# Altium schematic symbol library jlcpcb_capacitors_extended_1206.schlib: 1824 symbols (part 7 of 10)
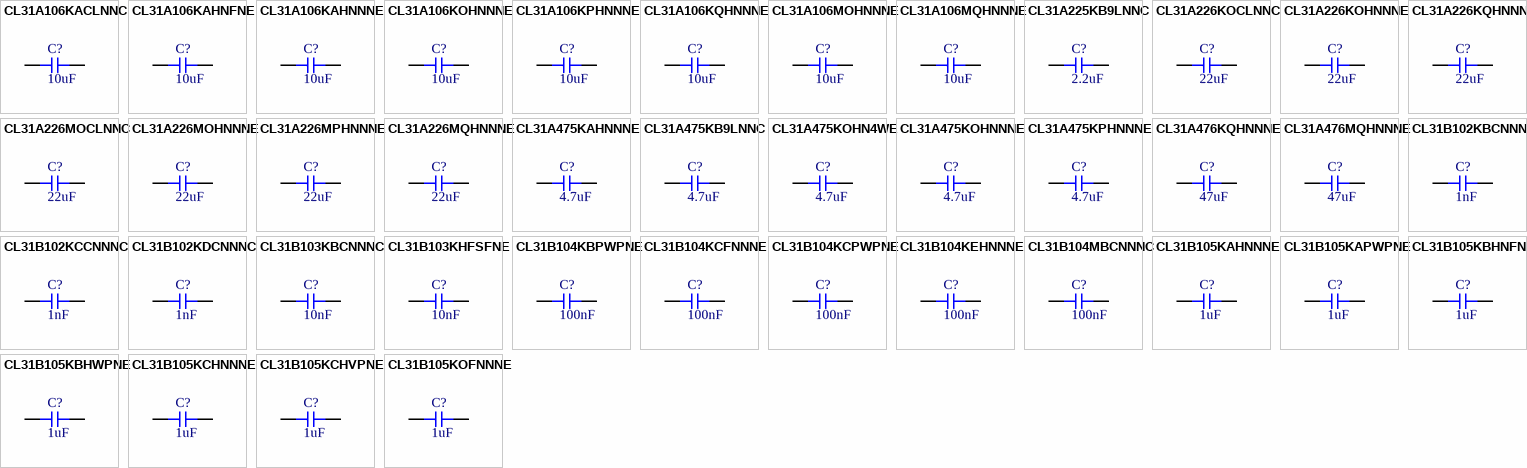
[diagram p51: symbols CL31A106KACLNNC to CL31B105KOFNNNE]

## CL31A475KAHNNNE
designator C?  Capacitance: 4.7uF  (hidden comment: *)
Capacitor, Ceramic (MLCC), 4.7uF, ±10%, 25V, X5R, ±10%, SMD 1206; Manufacturer: Samsung Electro-Mechanics; Manufacturer Part Number: CL31A475KAHNNNE
footprint CAP-1206 (1206 (3216M) Capacitor)
pins: 1, 2

## CL31A475KB9LNNC
designator C?  Capacitance: 4.7uF  (hidden comment: *)
Capacitor, Ceramic (MLCC), 4.7uF, ±10%, 50V, X5R, ±10%, SMD 1206; Manufacturer: Samsung Electro-Mechanics; Manufacturer Part Number: CL31A475KB9LNNC
footprint CAP-1206 (1206 (3216M) Capacitor)
pins: 1, 2

## CL31A475KOHN4WE
designator C?  Capacitance: 4.7uF  (hidden comment: *)
Capacitor, Ceramic (MLCC), 4.7uF, ±10%, 16V, X5R, ±10%, SMD 1206; Manufacturer: Samsung Electro-Mechanics; Manufacturer Part Number: CL31A475KOHN4WE
footprint CAP-1206 (1206 (3216M) Capacitor)
pins: 1, 2

## CL31A475KOHNNNE
designator C?  Capacitance: 4.7uF  (hidden comment: *)
Capacitor, Ceramic (MLCC), 4.7uF, ±10%, 16V, X5R, ±10%, SMD 1206; Manufacturer: Samsung Electro-Mechanics; Manufacturer Part Number: CL31A475KOHNNNE
footprint CAP-1206 (1206 (3216M) Capacitor)
pins: 1, 2

## CL31A475KPHNNNE
designator C?  Capacitance: 4.7uF  (hidden comment: *)
Capacitor, Ceramic (MLCC), 4.7uF, ±10%, 10V, X5R, ±10%, SMD 1206; Manufacturer: Samsung Electro-Mechanics; Manufacturer Part Number: CL31A475KPHNNNE
footprint CAP-1206 (1206 (3216M) Capacitor)
pins: 1, 2

## CL31A476KQHNNNE
designator C?  Capacitance: 47uF  (hidden comment: *)
Capacitor, Ceramic (MLCC), 47uF, ±10%, 6.3V, X5R, ±10%, SMD 1206; Manufacturer: Samsung Electro-Mechanics; Manufacturer Part Number: CL31A476KQHNNNE
footprint CAP-1206 (1206 (3216M) Capacitor)
pins: 1, 2

## CL31A476MQHNNNE
designator C?  Capacitance: 47uF  (hidden comment: *)
Capacitor, Ceramic (MLCC), 47uF, ±20%, 6.3V, X5R, ±20%, SMD 1206; Manufacturer: Samsung Electro-Mechanics; Manufacturer Part Number: CL31A476MQHNNNE
footprint CAP-1206 (1206 (3216M) Capacitor)
pins: 1, 2

## CL31B102KBCNNNC
designator C?  Capacitance: 1nF  (hidden comment: *)
Capacitor, Ceramic (MLCC), 1nF, ±10%, 50V, X7R, ±10%, SMD 1206; Manufacturer: Samsung Electro-Mechanics; Manufacturer Part Number: CL31B102KBCNNNC
footprint CAP-1206 (1206 (3216M) Capacitor)
pins: 1, 2

## CL31B102KCCNNNC
designator C?  Capacitance: 1nF  (hidden comment: *)
Capacitor, Ceramic (MLCC), 1nF, ±10%, 100V, X7R, ±10%, SMD 1206; Manufacturer: Samsung Electro-Mechanics; Manufacturer Part Number: CL31B102KCCNNNC
footprint CAP-1206 (1206 (3216M) Capacitor)
pins: 1, 2

## CL31B102KDCNNNC
designator C?  Capacitance: 1nF  (hidden comment: *)
Capacitor, Ceramic (MLCC), 1nF, ±10%, 200V, X7R, ±10%, SMD 1206; Manufacturer: Samsung Electro-Mechanics; Manufacturer Part Number: CL31B102KDCNNNC
footprint CAP-1206 (1206 (3216M) Capacitor)
pins: 1, 2

## CL31B103KBCNNNC
designator C?  Capacitance: 10nF  (hidden comment: *)
Capacitor, Ceramic (MLCC), 10nF, ±10%, 50V, X7R, ±10%, SMD 1206; Manufacturer: Samsung Electro-Mechanics; Manufacturer Part Number: CL31B103KBCNNNC
footprint CAP-1206 (1206 (3216M) Capacitor)
pins: 1, 2

## CL31B103KHFSFNE
designator C?  Capacitance: 10nF  (hidden comment: *)
Capacitor, Ceramic (MLCC), 10nF, ±10%, 630V, X7R, ±10%, SMD 1206; Manufacturer: Samsung Electro-Mechanics; Manufacturer Part Number: CL31B103KHFSFNE
footprint CAP-1206 (1206 (3216M) Capacitor)
pins: 1, 2

## CL31B104KBPWPNE
designator C?  Capacitance: 100nF  (hidden comment: *)
Capacitor, Ceramic (MLCC), 100nF, ±10%, 50V, X7R, ±10%, SMD 1206; Manufacturer: Samsung Electro-Mechanics; Manufacturer Part Number: CL31B104KBPWPNE
footprint CAP-1206 (1206 (3216M) Capacitor)
pins: 1, 2

## CL31B104KCFNNNE
designator C?  Capacitance: 100nF  (hidden comment: *)
Capacitor, Ceramic (MLCC), 100nF, ±10%, 100V, X7R, ±10%, SMD 1206; Manufacturer: Samsung Electro-Mechanics; Manufacturer Part Number: CL31B104KCFNNNE
footprint CAP-1206 (1206 (3216M) Capacitor)
pins: 1, 2

## CL31B104KCPWPNE
designator C?  Capacitance: 100nF  (hidden comment: *)
Capacitor, Ceramic (MLCC), 100nF, ±10%, 100V, X7R, ±10%, SMD 1206; Manufacturer: Samsung Electro-Mechanics; Manufacturer Part Number: CL31B104KCPWPNE
footprint CAP-1206 (1206 (3216M) Capacitor)
pins: 1, 2

## CL31B104KEHNNNE
designator C?  Capacitance: 100nF  (hidden comment: *)
Capacitor, Ceramic (MLCC), 100nF, ±10%, 250V, X7R, ±10%, SMD 1206; Manufacturer: Samsung Electro-Mechanics; Manufacturer Part Number: CL31B104KEHNNNE
footprint CAP-1206 (1206 (3216M) Capacitor)
pins: 1, 2

## CL31B104MBCNNNC
designator C?  Capacitance: 100nF  (hidden comment: *)
Capacitor, Ceramic (MLCC), 100nF, ±20%, 50V, X7R, ±20%, SMD 1206; Manufacturer: Samsung Electro-Mechanics; Manufacturer Part Number: CL31B104MBCNNNC
footprint CAP-1206 (1206 (3216M) Capacitor)
pins: 1, 2

## CL31B105KAHNNNE
designator C?  Capacitance: 1uF  (hidden comment: *)
Capacitor, Ceramic (MLCC), 1uF, ±10%, 25V, X7R, ±10%, SMD 1206; Manufacturer: Samsung Electro-Mechanics; Manufacturer Part Number: CL31B105KAHNNNE
footprint CAP-1206 (1206 (3216M) Capacitor)
pins: 1, 2

## CL31B105KAPWPNE
designator C?  Capacitance: 1uF  (hidden comment: *)
Capacitor, Ceramic (MLCC), 1uF, ±10%, 25V, X7R, ±10%, SMD 1206; Manufacturer: Samsung Electro-Mechanics; Manufacturer Part Number: CL31B105KAPWPNE
footprint CAP-1206 (1206 (3216M) Capacitor)
pins: 1, 2

## CL31B105KBHNFNE
designator C?  Capacitance: 1uF  (hidden comment: *)
Capacitor, Ceramic (MLCC), 1uF, ±10%, 50V, X7R, ±10%, SMD 1206; Manufacturer: Samsung Electro-Mechanics; Manufacturer Part Number: CL31B105KBHNFNE
footprint CAP-1206 (1206 (3216M) Capacitor)
pins: 1, 2

## CL31B105KBHWPNE
designator C?  Capacitance: 1uF  (hidden comment: *)
Capacitor, Ceramic (MLCC), 1uF, ±10%, 50V, X7R, ±10%, SMD 1206; Manufacturer: Samsung Electro-Mechanics; Manufacturer Part Number: CL31B105KBHWPNE
footprint CAP-1206 (1206 (3216M) Capacitor)
pins: 1, 2

## CL31B105KCHNNNE
designator C?  Capacitance: 1uF  (hidden comment: *)
Capacitor, Ceramic (MLCC), 1uF, ±10%, 100V, X7R, ±10%, SMD 1206; Manufacturer: Samsung Electro-Mechanics; Manufacturer Part Number: CL31B105KCHNNNE
footprint CAP-1206 (1206 (3216M) Capacitor)
pins: 1, 2

## CL31B105KCHVPNE
designator C?  Capacitance: 1uF  (hidden comment: *)
Capacitor, Ceramic (MLCC), 1uF, ±10%, 100V, X7R, ±10%, SMD 1206; Manufacturer: Samsung Electro-Mechanics; Manufacturer Part Number: CL31B105KCHVPNE
footprint CAP-1206 (1206 (3216M) Capacitor)
pins: 1, 2

## CL31B105KOFNNNE
designator C?  Capacitance: 1uF  (hidden comment: *)
Capacitor, Ceramic (MLCC), 1uF, ±10%, 16V, X7R, ±10%, SMD 1206; Manufacturer: Samsung Electro-Mechanics; Manufacturer Part Number: CL31B105KOFNNNE
footprint CAP-1206 (1206 (3216M) Capacitor)
pins: 1, 2

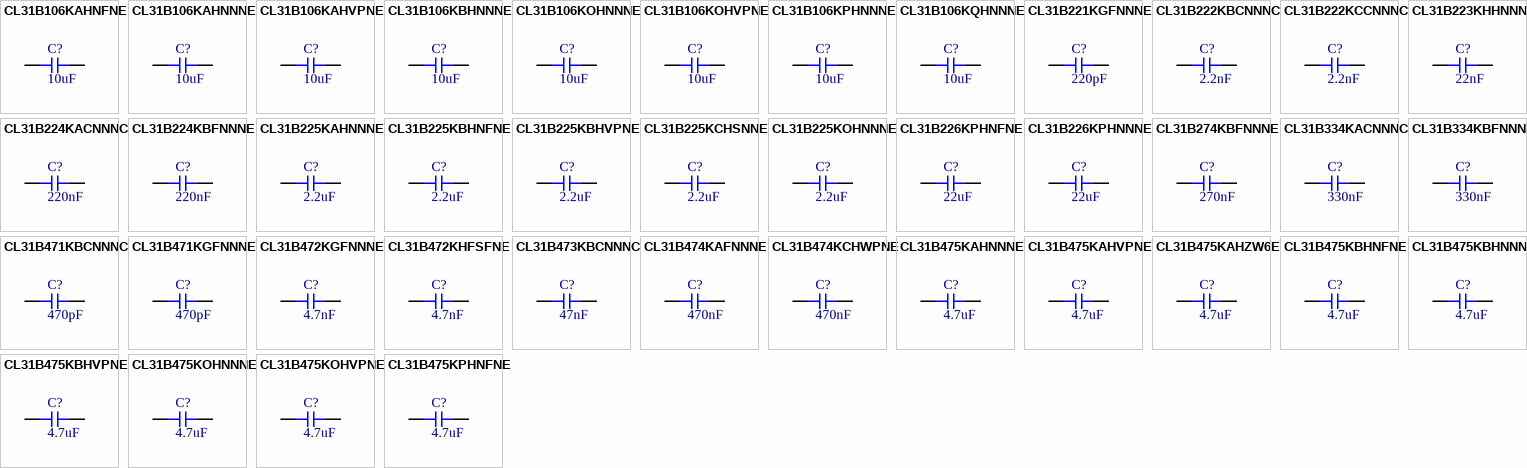
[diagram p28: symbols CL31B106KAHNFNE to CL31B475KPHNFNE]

## CL31B106KAHNFNE
designator C?  Capacitance: 10uF  (hidden comment: *)
Capacitor, Ceramic (MLCC), 10uF, ±10%, 25V, X7R, ±10%, SMD 1206; Manufacturer: Samsung Electro-Mechanics; Manufacturer Part Number: CL31B106KAHNFNE
footprint CAP-1206 (1206 (3216M) Capacitor)
pins: 1, 2

## CL31B106KAHNNNE
designator C?  Capacitance: 10uF  (hidden comment: *)
Capacitor, Ceramic (MLCC), 10uF, ±10%, 25V, X7R, ±10%, SMD 1206; Manufacturer: Samsung Electro-Mechanics; Manufacturer Part Number: CL31B106KAHNNNE
footprint CAP-1206 (1206 (3216M) Capacitor)
pins: 1, 2

## CL31B106KAHVPNE
designator C?  Capacitance: 10uF  (hidden comment: *)
Capacitor, Ceramic (MLCC), 10uF, ±10%, 25V, X7R, ±10%, SMD 1206; Manufacturer: Samsung Electro-Mechanics; Manufacturer Part Number: CL31B106KAHVPNE
footprint CAP-1206 (1206 (3216M) Capacitor)
pins: 1, 2

## CL31B106KBHNNNE
designator C?  Capacitance: 10uF  (hidden comment: *)
Capacitor, Ceramic (MLCC), 10uF, ±10%, 50V, X7R, ±10%, SMD 1206; Manufacturer: Samsung Electro-Mechanics; Manufacturer Part Number: CL31B106KBHNNNE
footprint CAP-1206 (1206 (3216M) Capacitor)
pins: 1, 2

## CL31B106KOHNNNE
designator C?  Capacitance: 10uF  (hidden comment: *)
Capacitor, Ceramic (MLCC), 10uF, ±10%, 16V, X7R, ±10%, SMD 1206; Manufacturer: Samsung Electro-Mechanics; Manufacturer Part Number: CL31B106KOHNNNE
footprint CAP-1206 (1206 (3216M) Capacitor)
pins: 1, 2

## CL31B106KOHVPNE
designator C?  Capacitance: 10uF  (hidden comment: *)
Capacitor, Ceramic (MLCC), 10uF, ±10%, 16V, X7R, ±10%, SMD 1206; Manufacturer: Samsung Electro-Mechanics; Manufacturer Part Number: CL31B106KOHVPNE
footprint CAP-1206 (1206 (3216M) Capacitor)
pins: 1, 2

## CL31B106KPHNNNE
designator C?  Capacitance: 10uF  (hidden comment: *)
Capacitor, Ceramic (MLCC), 10uF, ±10%, 10V, X7R, ±10%, SMD 1206; Manufacturer: Samsung Electro-Mechanics; Manufacturer Part Number: CL31B106KPHNNNE
footprint CAP-1206 (1206 (3216M) Capacitor)
pins: 1, 2

## CL31B106KQHNNNE
designator C?  Capacitance: 10uF  (hidden comment: *)
Capacitor, Ceramic (MLCC), 10uF, ±10%, 6.3V, X7R, ±10%, SMD 1206; Manufacturer: Samsung Electro-Mechanics; Manufacturer Part Number: CL31B106KQHNNNE
footprint CAP-1206 (1206 (3216M) Capacitor)
pins: 1, 2

## CL31B221KGFNNNE
designator C?  Capacitance: 220pF  (hidden comment: *)
Capacitor, Ceramic (MLCC), 220pF, ±10%, 500V, X7R, ±10%, SMD 1206; Manufacturer: Samsung Electro-Mechanics; Manufacturer Part Number: CL31B221KGFNNNE
footprint CAP-1206 (1206 (3216M) Capacitor)
pins: 1, 2

## CL31B222KBCNNNC
designator C?  Capacitance: 2.2nF  (hidden comment: *)
Capacitor, Ceramic (MLCC), 2.2nF, ±10%, 50V, X7R, ±10%, SMD 1206; Manufacturer: Samsung Electro-Mechanics; Manufacturer Part Number: CL31B222KBCNNNC
footprint CAP-1206 (1206 (3216M) Capacitor)
pins: 1, 2

## CL31B222KCCNNNC
designator C?  Capacitance: 2.2nF  (hidden comment: *)
Capacitor, Ceramic (MLCC), 2.2nF, ±10%, 100V, X7R, ±10%, SMD 1206; Manufacturer: Samsung Electro-Mechanics; Manufacturer Part Number: CL31B222KCCNNNC
footprint CAP-1206 (1206 (3216M) Capacitor)
pins: 1, 2

## CL31B223KHHNNNE
designator C?  Capacitance: 22nF  (hidden comment: *)
Capacitor, Ceramic (MLCC), 22nF, ±10%, 630V, X7R, ±10%, SMD 1206; Manufacturer: Samsung Electro-Mechanics; Manufacturer Part Number: CL31B223KHHNNNE
footprint CAP-1206 (1206 (3216M) Capacitor)
pins: 1, 2

## CL31B224KACNNNC
designator C?  Capacitance: 220nF  (hidden comment: *)
Capacitor, Ceramic (MLCC), 220nF, ±10%, 25V, X7R, ±10%, SMD 1206; Manufacturer: Samsung Electro-Mechanics; Manufacturer Part Number: CL31B224KACNNNC
footprint CAP-1206 (1206 (3216M) Capacitor)
pins: 1, 2

## CL31B224KBFNNNE
designator C?  Capacitance: 220nF  (hidden comment: *)
Capacitor, Ceramic (MLCC), 220nF, ±10%, 50V, X7R, ±10%, SMD 1206; Manufacturer: Samsung Electro-Mechanics; Manufacturer Part Number: CL31B224KBFNNNE
footprint CAP-1206 (1206 (3216M) Capacitor)
pins: 1, 2

## CL31B225KAHNNNE
designator C?  Capacitance: 2.2uF  (hidden comment: *)
Capacitor, Ceramic (MLCC), 2.2uF, ±10%, 25V, X7R, ±10%, SMD 1206; Manufacturer: Samsung Electro-Mechanics; Manufacturer Part Number: CL31B225KAHNNNE
footprint CAP-1206 (1206 (3216M) Capacitor)
pins: 1, 2

## CL31B225KBHNFNE
designator C?  Capacitance: 2.2uF  (hidden comment: *)
Capacitor, Ceramic (MLCC), 2.2uF, ±10%, 50V, X7R, ±10%, SMD 1206; Manufacturer: Samsung Electro-Mechanics; Manufacturer Part Number: CL31B225KBHNFNE
footprint CAP-1206 (1206 (3216M) Capacitor)
pins: 1, 2

## CL31B225KBHVPNE
designator C?  Capacitance: 2.2uF  (hidden comment: *)
Capacitor, Ceramic (MLCC), 2.2uF, ±10%, 50V, X7R, ±10%, SMD 1206; Manufacturer: Samsung Electro-Mechanics; Manufacturer Part Number: CL31B225KBHVPNE
footprint CAP-1206 (1206 (3216M) Capacitor)
pins: 1, 2

## CL31B225KCHSNNE
designator C?  Capacitance: 2.2uF  (hidden comment: *)
Capacitor, Ceramic (MLCC), 2.2uF, ±10%, 100V, X7R, ±10%, SMD 1206; Manufacturer: Samsung Electro-Mechanics; Manufacturer Part Number: CL31B225KCHSNNE
footprint CAP-1206 (1206 (3216M) Capacitor)
pins: 1, 2

## CL31B225KOHNNNE
designator C?  Capacitance: 2.2uF  (hidden comment: *)
Capacitor, Ceramic (MLCC), 2.2uF, ±10%, 16V, X7R, ±10%, SMD 1206; Manufacturer: Samsung Electro-Mechanics; Manufacturer Part Number: CL31B225KOHNNNE
footprint CAP-1206 (1206 (3216M) Capacitor)
pins: 1, 2

## CL31B226KPHNFNE
designator C?  Capacitance: 22uF  (hidden comment: *)
Capacitor, Ceramic (MLCC), 22uF, ±10%, 10V, X7R, ±10%, SMD 1206; Manufacturer: Samsung Electro-Mechanics; Manufacturer Part Number: CL31B226KPHNFNE
footprint CAP-1206 (1206 (3216M) Capacitor)
pins: 1, 2

## CL31B226KPHNNNE
designator C?  Capacitance: 22uF  (hidden comment: *)
Capacitor, Ceramic (MLCC), 22uF, ±10%, 10V, X7R, ±10%, SMD 1206; Manufacturer: Samsung Electro-Mechanics; Manufacturer Part Number: CL31B226KPHNNNE
footprint CAP-1206 (1206 (3216M) Capacitor)
pins: 1, 2

## CL31B274KBFNNNE
designator C?  Capacitance: 270nF  (hidden comment: *)
Capacitor, Ceramic (MLCC), 270nF, ±10%, 50V, X7R, ±10%, SMD 1206; Manufacturer: Samsung Electro-Mechanics; Manufacturer Part Number: CL31B274KBFNNNE
footprint CAP-1206 (1206 (3216M) Capacitor)
pins: 1, 2

## CL31B334KACNNNC
designator C?  Capacitance: 330nF  (hidden comment: *)
Capacitor, Ceramic (MLCC), 330nF, ±10%, 25V, X7R, ±10%, SMD 1206; Manufacturer: Samsung Electro-Mechanics; Manufacturer Part Number: CL31B334KACNNNC
footprint CAP-1206 (1206 (3216M) Capacitor)
pins: 1, 2

## CL31B334KBFNNNE
designator C?  Capacitance: 330nF  (hidden comment: *)
Capacitor, Ceramic (MLCC), 330nF, ±10%, 50V, X7R, ±10%, SMD 1206; Manufacturer: Samsung Electro-Mechanics; Manufacturer Part Number: CL31B334KBFNNNE
footprint CAP-1206 (1206 (3216M) Capacitor)
pins: 1, 2

## CL31B471KBCNNNC
designator C?  Capacitance: 470pF  (hidden comment: *)
Capacitor, Ceramic (MLCC), 470pF, ±10%, 50V, X7R, ±10%, SMD 1206; Manufacturer: Samsung Electro-Mechanics; Manufacturer Part Number: CL31B471KBCNNNC
footprint CAP-1206 (1206 (3216M) Capacitor)
pins: 1, 2

## CL31B471KGFNNNE
designator C?  Capacitance: 470pF  (hidden comment: *)
Capacitor, Ceramic (MLCC), 470pF, ±10%, 500V, X7R, ±10%, SMD 1206; Manufacturer: Samsung Electro-Mechanics; Manufacturer Part Number: CL31B471KGFNNNE
footprint CAP-1206 (1206 (3216M) Capacitor)
pins: 1, 2

## CL31B472KGFNNNE
designator C?  Capacitance: 4.7nF  (hidden comment: *)
Capacitor, Ceramic (MLCC), 4.7nF, ±10%, 500V, X7R, ±10%, SMD 1206; Manufacturer: Samsung Electro-Mechanics; Manufacturer Part Number: CL31B472KGFNNNE
footprint CAP-1206 (1206 (3216M) Capacitor)
pins: 1, 2

## CL31B472KHFSFNE
designator C?  Capacitance: 4.7nF  (hidden comment: *)
Capacitor, Ceramic (MLCC), 4.7nF, ±10%, 630V, X7R, ±10%, SMD 1206; Manufacturer: Samsung Electro-Mechanics; Manufacturer Part Number: CL31B472KHFSFNE
footprint CAP-1206 (1206 (3216M) Capacitor)
pins: 1, 2

## CL31B473KBCNNNC
designator C?  Capacitance: 47nF  (hidden comment: *)
Capacitor, Ceramic (MLCC), 47nF, ±10%, 50V, X7R, ±10%, SMD 1206; Manufacturer: Samsung Electro-Mechanics; Manufacturer Part Number: CL31B473KBCNNNC
footprint CAP-1206 (1206 (3216M) Capacitor)
pins: 1, 2

## CL31B474KAFNNNE
designator C?  Capacitance: 470nF  (hidden comment: *)
Capacitor, Ceramic (MLCC), 470nF, ±10%, 25V, X7R, ±10%, SMD 1206; Manufacturer: Samsung Electro-Mechanics; Manufacturer Part Number: CL31B474KAFNNNE
footprint CAP-1206 (1206 (3216M) Capacitor)
pins: 1, 2

## CL31B474KCHWPNE
designator C?  Capacitance: 470nF  (hidden comment: *)
Capacitor, Ceramic (MLCC), 470nF, ±10%, 100V, X7R, ±10%, SMD 1206; Manufacturer: Samsung Electro-Mechanics; Manufacturer Part Number: CL31B474KCHWPNE
footprint CAP-1206 (1206 (3216M) Capacitor)
pins: 1, 2

## CL31B475KAHNNNE
designator C?  Capacitance: 4.7uF  (hidden comment: *)
Capacitor, Ceramic (MLCC), 4.7uF, ±10%, 25V, X7R, ±10%, SMD 1206; Manufacturer: Samsung Electro-Mechanics; Manufacturer Part Number: CL31B475KAHNNNE
footprint CAP-1206 (1206 (3216M) Capacitor)
pins: 1, 2

## CL31B475KAHVPNE
designator C?  Capacitance: 4.7uF  (hidden comment: *)
Capacitor, Ceramic (MLCC), 4.7uF, ±10%, 25V, X7R, ±10%, SMD 1206; Manufacturer: Samsung Electro-Mechanics; Manufacturer Part Number: CL31B475KAHVPNE
footprint CAP-1206 (1206 (3216M) Capacitor)
pins: 1, 2

## CL31B475KAHZW6E
designator C?  Capacitance: 4.7uF  (hidden comment: *)
Capacitor, Ceramic (MLCC), 4.7uF, ±10%, 25V, X7R, ±10%, SMD 1206; Manufacturer: Samsung Electro-Mechanics; Manufacturer Part Number: CL31B475KAHZW6E
footprint CAP-1206 (1206 (3216M) Capacitor)
pins: 1, 2

## CL31B475KBHNFNE
designator C?  Capacitance: 4.7uF  (hidden comment: *)
Capacitor, Ceramic (MLCC), 4.7uF, ±10%, 50V, X7R, ±10%, SMD 1206; Manufacturer: Samsung Electro-Mechanics; Manufacturer Part Number: CL31B475KBHNFNE
footprint CAP-1206 (1206 (3216M) Capacitor)
pins: 1, 2

## CL31B475KBHNNNE
designator C?  Capacitance: 4.7uF  (hidden comment: *)
Capacitor, Ceramic (MLCC), 4.7uF, ±10%, 50V, X7R, ±10%, SMD 1206; Manufacturer: Samsung Electro-Mechanics; Manufacturer Part Number: CL31B475KBHNNNE
footprint CAP-1206 (1206 (3216M) Capacitor)
pins: 1, 2

## CL31B475KBHVPNE
designator C?  Capacitance: 4.7uF  (hidden comment: *)
Capacitor, Ceramic (MLCC), 4.7uF, ±10%, 50V, X7R, ±10%, SMD 1206; Manufacturer: Samsung Electro-Mechanics; Manufacturer Part Number: CL31B475KBHVPNE
footprint CAP-1206 (1206 (3216M) Capacitor)
pins: 1, 2

## CL31B475KOHNNNE
designator C?  Capacitance: 4.7uF  (hidden comment: *)
Capacitor, Ceramic (MLCC), 4.7uF, ±10%, 16V, X7R, ±10%, SMD 1206; Manufacturer: Samsung Electro-Mechanics; Manufacturer Part Number: CL31B475KOHNNNE
footprint CAP-1206 (1206 (3216M) Capacitor)
pins: 1, 2

## CL31B475KOHVPNE
designator C?  Capacitance: 4.7uF  (hidden comment: *)
Capacitor, Ceramic (MLCC), 4.7uF, ±10%, 16V, X7R, ±10%, SMD 1206; Manufacturer: Samsung Electro-Mechanics; Manufacturer Part Number: CL31B475KOHVPNE
footprint CAP-1206 (1206 (3216M) Capacitor)
pins: 1, 2

## CL31B475KPHNFNE
designator C?  Capacitance: 4.7uF  (hidden comment: *)
Capacitor, Ceramic (MLCC), 4.7uF, ±10%, 10V, X7R, ±10%, SMD 1206; Manufacturer: Samsung Electro-Mechanics; Manufacturer Part Number: CL31B475KPHNFNE
footprint CAP-1206 (1206 (3216M) Capacitor)
pins: 1, 2

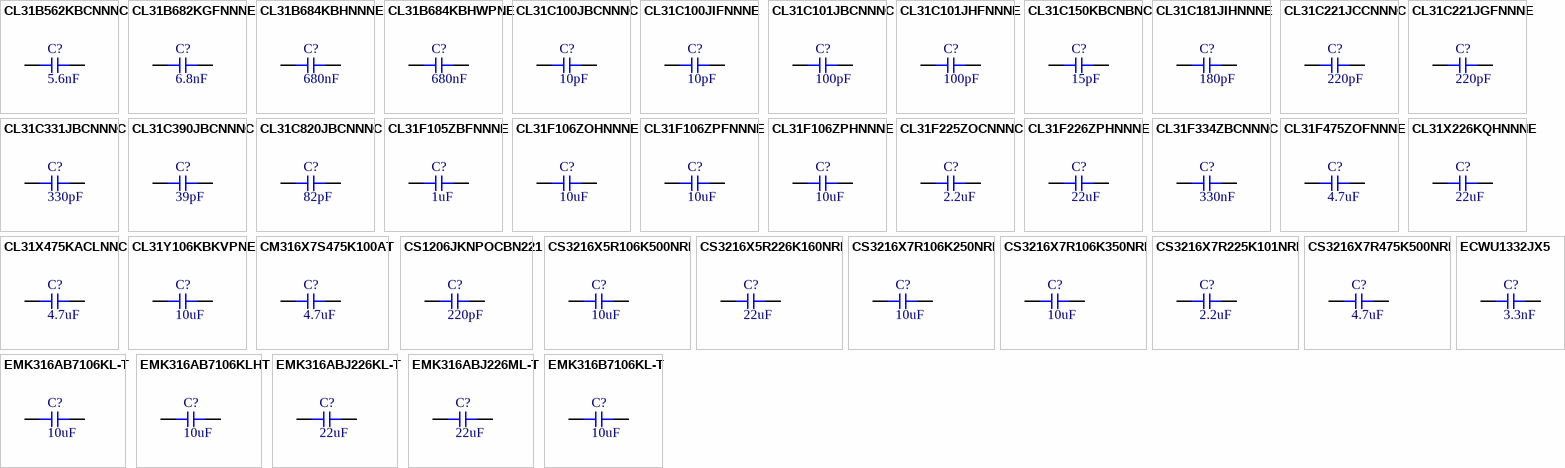
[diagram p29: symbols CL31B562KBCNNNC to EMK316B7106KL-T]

## CL31B562KBCNNNC
designator C?  Capacitance: 5.6nF  (hidden comment: *)
Capacitor, Ceramic (MLCC), 5.6nF, ±10%, 50V, X7R, ±10%, SMD 1206; Manufacturer: Samsung Electro-Mechanics; Manufacturer Part Number: CL31B562KBCNNNC
footprint CAP-1206 (1206 (3216M) Capacitor)
pins: 1, 2

## CL31B682KGFNNNE
designator C?  Capacitance: 6.8nF  (hidden comment: *)
Capacitor, Ceramic (MLCC), 6.8nF, ±10%, 500V, X7R, ±10%, SMD 1206; Manufacturer: Samsung Electro-Mechanics; Manufacturer Part Number: CL31B682KGFNNNE
footprint CAP-1206 (1206 (3216M) Capacitor)
pins: 1, 2

## CL31B684KBHNNNE
designator C?  Capacitance: 680nF  (hidden comment: *)
Capacitor, Ceramic (MLCC), 680nF, ±10%, 50V, X7R, ±10%, SMD 1206; Manufacturer: Samsung Electro-Mechanics; Manufacturer Part Number: CL31B684KBHNNNE
footprint CAP-1206 (1206 (3216M) Capacitor)
pins: 1, 2

## CL31B684KBHWPNE
designator C?  Capacitance: 680nF  (hidden comment: *)
Capacitor, Ceramic (MLCC), 680nF, ±10%, 50V, X7R, ±10%, SMD 1206; Manufacturer: Samsung Electro-Mechanics; Manufacturer Part Number: CL31B684KBHWPNE
footprint CAP-1206 (1206 (3216M) Capacitor)
pins: 1, 2

## CL31C100JBCNNNC
designator C?  Capacitance: 10pF  (hidden comment: *)
Capacitor, Ceramic (MLCC), 10pF, ±5%, 50V, C0G, ±5%, SMD 1206; Manufacturer: Samsung Electro-Mechanics; Manufacturer Part Number: CL31C100JBCNNNC
footprint CAP-1206 (1206 (3216M) Capacitor)
pins: 1, 2

## CL31C100JIFNNNE
designator C?  Capacitance: 10pF  (hidden comment: *)
Capacitor, Ceramic (MLCC), 10pF, ±5%, 1kV, C0G, ±5%, SMD 1206; Manufacturer: Samsung Electro-Mechanics; Manufacturer Part Number: CL31C100JIFNNNE
footprint CAP-1206 (1206 (3216M) Capacitor)
pins: 1, 2

## CL31C101JBCNNNC
designator C?  Capacitance: 100pF  (hidden comment: *)
Capacitor, Ceramic (MLCC), 100pF, ±5%, 50V, C0G, ±5%, SMD 1206; Manufacturer: Samsung Electro-Mechanics; Manufacturer Part Number: CL31C101JBCNNNC
footprint CAP-1206 (1206 (3216M) Capacitor)
pins: 1, 2

## CL31C101JHFNNNE
designator C?  Capacitance: 100pF  (hidden comment: *)
Capacitor, Ceramic (MLCC), 100pF, ±5%, 630V, C0G, ±5%, SMD 1206; Manufacturer: Samsung Electro-Mechanics; Manufacturer Part Number: CL31C101JHFNNNE
footprint CAP-1206 (1206 (3216M) Capacitor)
pins: 1, 2

## CL31C150KBCNBNC
designator C?  Capacitance: 15pF  (hidden comment: *)
Capacitor, Ceramic (MLCC), 15pF, ±10%, 50V, C0G, ±10%, SMD 1206; Manufacturer: Samsung Electro-Mechanics; Manufacturer Part Number: CL31C150KBCNBNC
footprint CAP-1206 (1206 (3216M) Capacitor)
pins: 1, 2

## CL31C181JIHNNNE
designator C?  Capacitance: 180pF  (hidden comment: *)
Capacitor, Ceramic (MLCC), 180pF, ±5%, 1kV, C0G, ±5%, SMD 1206; Manufacturer: Samsung Electro-Mechanics; Manufacturer Part Number: CL31C181JIHNNNE
footprint CAP-1206 (1206 (3216M) Capacitor)
pins: 1, 2

## CL31C221JCCNNNC
designator C?  Capacitance: 220pF  (hidden comment: *)
Capacitor, Ceramic (MLCC), 220pF, ±5%, 100V, C0G, ±5%, SMD 1206; Manufacturer: Samsung Electro-Mechanics; Manufacturer Part Number: CL31C221JCCNNNC
footprint CAP-1206 (1206 (3216M) Capacitor)
pins: 1, 2

## CL31C221JGFNNNE
designator C?  Capacitance: 220pF  (hidden comment: *)
Capacitor, Ceramic (MLCC), 220pF, ±10%, 500V, C0G, ±10%, SMD 1206; Manufacturer: Samsung Electro-Mechanics; Manufacturer Part Number: CL31C221JGFNNNE
footprint CAP-1206 (1206 (3216M) Capacitor)
pins: 1, 2

## CL31C331JBCNNNC
designator C?  Capacitance: 330pF  (hidden comment: *)
Capacitor, Ceramic (MLCC), 330pF, ±5%, 50V, C0G, ±5%, SMD 1206; Manufacturer: Samsung Electro-Mechanics; Manufacturer Part Number: CL31C331JBCNNNC
footprint CAP-1206 (1206 (3216M) Capacitor)
pins: 1, 2

## CL31C390JBCNNNC
designator C?  Capacitance: 39pF  (hidden comment: *)
Capacitor, Ceramic (MLCC), 39pF, ±5%, 50V, C0G, ±5%, SMD 1206; Manufacturer: Samsung Electro-Mechanics; Manufacturer Part Number: CL31C390JBCNNNC
footprint CAP-1206 (1206 (3216M) Capacitor)
pins: 1, 2

## CL31C820JBCNNNC
designator C?  Capacitance: 82pF  (hidden comment: *)
Capacitor, Ceramic (MLCC), 82pF, ±5%, 50V, C0G, ±5%, SMD 1206; Manufacturer: Samsung Electro-Mechanics; Manufacturer Part Number: CL31C820JBCNNNC
footprint CAP-1206 (1206 (3216M) Capacitor)
pins: 1, 2

## CL31F105ZBFNNNE
designator C?  Capacitance: 1uF  (hidden comment: *)
Capacitor, Ceramic (MLCC), 1uF, 50V, Y5V, SMD 1206; Manufacturer: Samsung Electro-Mechanics; Manufacturer Part Number: CL31F105ZBFNNNE; Temperature Rating: -20%~+80%
footprint CAP-1206 (1206 (3216M) Capacitor)
pins: 1, 2

## CL31F106ZOHNNNE
designator C?  Capacitance: 10uF  (hidden comment: *)
Capacitor, Ceramic (MLCC), 10uF, 16V, Y5V, SMD 1206; Manufacturer: Samsung Electro-Mechanics; Manufacturer Part Number: CL31F106ZOHNNNE; Temperature Rating: -20%~+80%
footprint CAP-1206 (1206 (3216M) Capacitor)
pins: 1, 2

## CL31F106ZPFNNNE
designator C?  Capacitance: 10uF  (hidden comment: *)
Capacitor, Ceramic (MLCC), 10uF, 10V, Y5V, SMD 1206; Manufacturer: Samsung Electro-Mechanics; Manufacturer Part Number: CL31F106ZPFNNNE; Temperature Rating: -20%~+80%
footprint CAP-1206 (1206 (3216M) Capacitor)
pins: 1, 2

## CL31F106ZPHNNNE
designator C?  Capacitance: 10uF  (hidden comment: *)
Capacitor, Ceramic (MLCC), 10uF, 10V, Y5V, SMD 1206; Manufacturer: Samsung Electro-Mechanics; Manufacturer Part Number: CL31F106ZPHNNNE; Temperature Rating: -20%~+80%
footprint CAP-1206 (1206 (3216M) Capacitor)
pins: 1, 2

## CL31F225ZOCNNNC
designator C?  Capacitance: 2.2uF  (hidden comment: *)
Capacitor, Ceramic (MLCC), 2.2uF, 16V, Y5V, SMD 1206; Manufacturer: Samsung Electro-Mechanics; Manufacturer Part Number: CL31F225ZOCNNNC; Temperature Rating: -20%~+80%
footprint CAP-1206 (1206 (3216M) Capacitor)
pins: 1, 2

## CL31F226ZPHNNNE
designator C?  Capacitance: 22uF  (hidden comment: *)
Capacitor, Ceramic (MLCC), 22uF, 10V, Y5V, SMD 1206; Manufacturer: Samsung Electro-Mechanics; Manufacturer Part Number: CL31F226ZPHNNNE; Temperature Rating: -20%~+80%
footprint CAP-1206 (1206 (3216M) Capacitor)
pins: 1, 2

## CL31F334ZBCNNNC
designator C?  Capacitance: 330nF  (hidden comment: *)
Capacitor, Ceramic (MLCC), 330nF, 50V, Y5V, SMD 1206; Manufacturer: Samsung Electro-Mechanics; Manufacturer Part Number: CL31F334ZBCNNNC; Temperature Rating: -20%~+80%
footprint CAP-1206 (1206 (3216M) Capacitor)
pins: 1, 2

## CL31F475ZOFNNNE
designator C?  Capacitance: 4.7uF  (hidden comment: *)
Capacitor, Ceramic (MLCC), 4.7uF, 16V, Y5V, SMD 1206; Manufacturer: Samsung Electro-Mechanics; Manufacturer Part Number: CL31F475ZOFNNNE; Temperature Rating: -20%~+80%
footprint CAP-1206 (1206 (3216M) Capacitor)
pins: 1, 2

## CL31X226KQHNNNE
designator C?  Capacitance: 22uF  (hidden comment: *)
Capacitor, Ceramic (MLCC), 22uF, ±10%, 6.3V, X6S, ±10%, SMD 1206; Manufacturer: Samsung Electro-Mechanics; Manufacturer Part Number: CL31X226KQHNNNE
footprint CAP-1206 (1206 (3216M) Capacitor)
pins: 1, 2

## CL31X475KACLNNC
designator C?  Capacitance: 4.7uF  (hidden comment: *)
Capacitor, Ceramic (MLCC), 4.7uF, ±10%, 25V, X6S, ±10%, SMD 1206; Manufacturer: Samsung Electro-Mechanics; Manufacturer Part Number: CL31X475KACLNNC
footprint CAP-1206 (1206 (3216M) Capacitor)
pins: 1, 2

## CL31Y106KBKVPNE
designator C?  Capacitance: 10uF  (hidden comment: *)
Capacitor, Ceramic (MLCC), 10uF, ±10%, 50V, ±10%, SMD 1206; Manufacturer: Samsung Electro-Mechanics; Manufacturer Part Number: CL31Y106KBKVPNE
footprint CAP-1206 (1206 (3216M) Capacitor)
pins: 1, 2

## CM316X7S475K100AT
designator C?  Capacitance: 4.7uF  (hidden comment: *)
Capacitor, Ceramic (MLCC), 4.7uF, ±10%, 100V, X7S, ±10%, SMD 1206; Manufacturer: Kyocera; Manufacturer Part Number: CM316X7S475K100AT
footprint CAP-1206 (1206 (3216M) Capacitor)
pins: 1, 2

## CS1206JKNPOCBN221
designator C?  Capacitance: 220pF  (hidden comment: *)
Capacitor, Ceramic (MLCC), 220pF, ±5%, 1kV, NP0, ±5%, SMD 1206; Manufacturer: YAGEO; Manufacturer Part Number: CS1206JKNPOCBN221
footprint CAP-1206 (1206 (3216M) Capacitor)
pins: 1, 2

## CS3216X5R106K500NRI
designator C?  Capacitance: 10uF  (hidden comment: *)
Capacitor, Ceramic (MLCC), 10uF, ±10%, 50V, X5R, ±10%, SMD 1206; Manufacturer: Samwha Capacitor; Manufacturer Part Number: CS3216X5R106K500NRI
footprint CAP-1206 (1206 (3216M) Capacitor)
pins: 1, 2

## CS3216X5R226K160NRI
designator C?  Capacitance: 22uF  (hidden comment: *)
Capacitor, Ceramic (MLCC), 22uF, ±10%, 16V, X5R, ±10%, SMD 1206; Manufacturer: Samwha Capacitor; Manufacturer Part Number: CS3216X5R226K160NRI
footprint CAP-1206 (1206 (3216M) Capacitor)
pins: 1, 2

## CS3216X7R106K250NRI
designator C?  Capacitance: 10uF  (hidden comment: *)
Capacitor, Ceramic (MLCC), 10uF, ±10%, 25V, X7R, ±10%, SMD 1206; Manufacturer: Samwha Capacitor; Manufacturer Part Number: CS3216X7R106K250NRI
footprint CAP-1206 (1206 (3216M) Capacitor)
pins: 1, 2

## CS3216X7R106K350NRI
designator C?  Capacitance: 10uF  (hidden comment: *)
Capacitor, Ceramic (MLCC), 10uF, ±10%, 35V, ±10%, SMD 1206; Manufacturer: Samwha Capacitor; Manufacturer Part Number: CS3216X7R106K350NRI
footprint CAP-1206 (1206 (3216M) Capacitor)
pins: 1, 2

## CS3216X7R225K101NRI
designator C?  Capacitance: 2.2uF  (hidden comment: *)
Capacitor, Ceramic (MLCC), 2.2uF, ±10%, 100V, ±10%, SMD 1206; Manufacturer: Samwha Capacitor; Manufacturer Part Number: CS3216X7R225K101NRI
footprint CAP-1206 (1206 (3216M) Capacitor)
pins: 1, 2

## CS3216X7R475K500NRI
designator C?  Capacitance: 4.7uF  (hidden comment: *)
Capacitor, Ceramic (MLCC), 4.7uF, ±10%, 50V, X7R, ±10%, SMD 1206; Manufacturer: Samwha Capacitor; Manufacturer Part Number: CS3216X7R475K500NRI
footprint CAP-1206 (1206 (3216M) Capacitor)
pins: 1, 2

## ECWU1332JX5
designator C?  Capacitance: 3.3nF  (hidden comment: *)
Capacitor, Ceramic (MLCC), 3.3nF, ±5%, 100V, PEN, ±5%, SMD 1206; Manufacturer: PANASONIC; Manufacturer Part Number: ECWU1332JX5
footprint CAP-1206 (1206 (3216M) Capacitor)
pins: 1, 2

## EMK316AB7106KL-T
designator C?  Capacitance: 10uF  (hidden comment: *)
Capacitor, Ceramic (MLCC), 10uF, ±10%, 16V, X7R, ±10%, SMD 1206; Manufacturer: Taiyo Yuden; Manufacturer Part Number: EMK316AB7106KL-T
footprint CAP-1206 (1206 (3216M) Capacitor)
pins: 1, 2

## EMK316AB7106KLHT
designator C?  Capacitance: 10uF  (hidden comment: *)
Capacitor, Ceramic (MLCC), 10uF, ±10%, 16V, X7R, ±10%, SMD 1206; Manufacturer: Taiyo Yuden; Manufacturer Part Number: EMK316AB7106KLHT
footprint CAP-1206 (1206 (3216M) Capacitor)
pins: 1, 2

## EMK316ABJ226KL-T
designator C?  Capacitance: 22uF  (hidden comment: *)
Capacitor, Ceramic (MLCC), 22uF, ±10%, 16V, X5R, ±10%, SMD 1206; Manufacturer: Taiyo Yuden; Manufacturer Part Number: EMK316ABJ226KL-T
footprint CAP-1206 (1206 (3216M) Capacitor)
pins: 1, 2

## EMK316ABJ226ML-T
designator C?  Capacitance: 22uF  (hidden comment: *)
Capacitor, Ceramic (MLCC), 22uF, ±20%, 16V, X5R, ±20%, SMD 1206; Manufacturer: Taiyo Yuden; Manufacturer Part Number: EMK316ABJ226ML-T
footprint CAP-1206 (1206 (3216M) Capacitor)
pins: 1, 2

## EMK316B7106KL-T
designator C?  Capacitance: 10uF  (hidden comment: *)
Capacitor, Ceramic (MLCC), 10uF, ±10%, 16V, X7R, ±10%, SMD 1206; Manufacturer: Taiyo Yuden; Manufacturer Part Number: EMK316B7106KL-T
footprint CAP-1206 (1206 (3216M) Capacitor)
pins: 1, 2

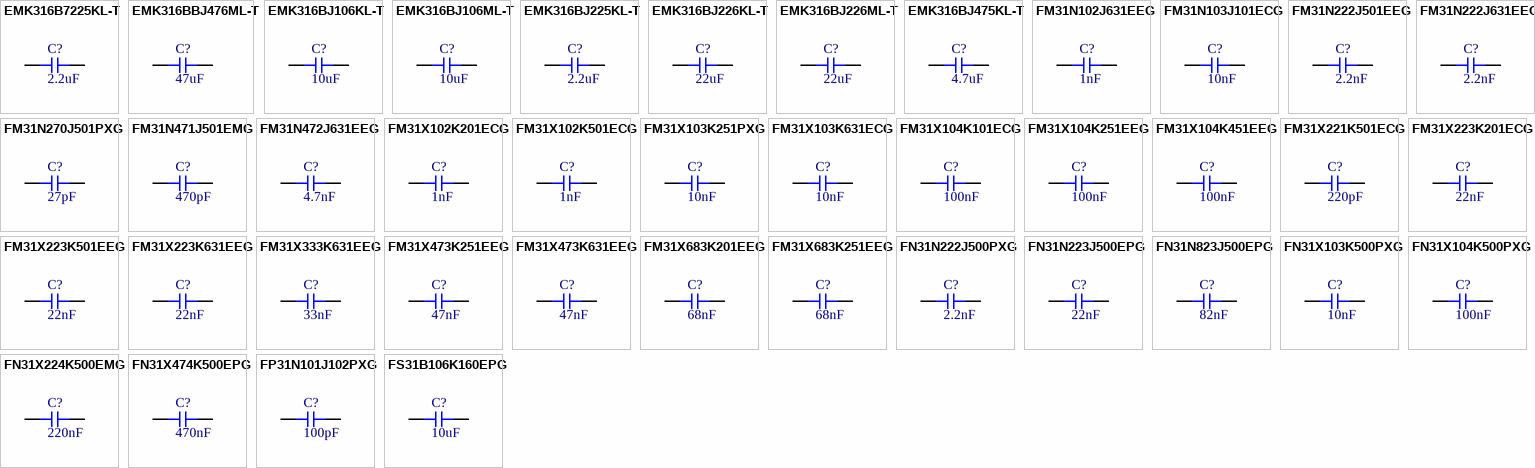
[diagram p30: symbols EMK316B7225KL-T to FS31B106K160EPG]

## EMK316B7225KL-T
designator C?  Capacitance: 2.2uF  (hidden comment: *)
Capacitor, Ceramic (MLCC), 2.2uF, ±10%, 16V, X7R, ±10%, SMD 1206; Manufacturer: Taiyo Yuden; Manufacturer Part Number: EMK316B7225KL-T
footprint CAP-1206 (1206 (3216M) Capacitor)
pins: 1, 2

## EMK316BBJ476ML-T
designator C?  Capacitance: 47uF  (hidden comment: *)
Capacitor, Ceramic (MLCC), 47uF, ±20%, 16V, X5R, ±20%, SMD 1206; Manufacturer: Taiyo Yuden; Manufacturer Part Number: EMK316BBJ476ML-T
footprint CAP-1206 (1206 (3216M) Capacitor)
pins: 1, 2

## EMK316BJ106KL-T
designator C?  Capacitance: 10uF  (hidden comment: *)
Capacitor, Ceramic (MLCC), 10uF, ±10%, 16V, X5R, ±10%, SMD 1206; Manufacturer: Taiyo Yuden; Manufacturer Part Number: EMK316BJ106KL-T
footprint CAP-1206 (1206 (3216M) Capacitor)
pins: 1, 2

## EMK316BJ106ML-T
designator C?  Capacitance: 10uF  (hidden comment: *)
Capacitor, Ceramic (MLCC), 10uF, ±20%, 16V, X5R, ±20%, SMD 1206; Manufacturer: Taiyo Yuden; Manufacturer Part Number: EMK316BJ106ML-T
footprint CAP-1206 (1206 (3216M) Capacitor)
pins: 1, 2

## EMK316BJ225KL-T
designator C?  Capacitance: 2.2uF  (hidden comment: *)
Capacitor, Ceramic (MLCC), 2.2uF, ±10%, 16V, X5R, ±10%, SMD 1206; Manufacturer: Taiyo Yuden; Manufacturer Part Number: EMK316BJ225KL-T
footprint CAP-1206 (1206 (3216M) Capacitor)
pins: 1, 2

## EMK316BJ226KL-T
designator C?  Capacitance: 22uF  (hidden comment: *)
Capacitor, Ceramic (MLCC), 22uF, ±10%, 16V, X5R, ±10%, SMD 1206; Manufacturer: Taiyo Yuden; Manufacturer Part Number: EMK316BJ226KL-T
footprint CAP-1206 (1206 (3216M) Capacitor)
pins: 1, 2

## EMK316BJ226ML-T
designator C?  Capacitance: 22uF  (hidden comment: *)
Capacitor, Ceramic (MLCC), 22uF, ±20%, 16V, X5R, ±20%, SMD 1206; Manufacturer: Taiyo Yuden; Manufacturer Part Number: EMK316BJ226ML-T
footprint CAP-1206 (1206 (3216M) Capacitor)
pins: 1, 2

## EMK316BJ475KL-T
designator C?  Capacitance: 4.7uF  (hidden comment: *)
Capacitor, Ceramic (MLCC), 4.7uF, ±10%, 16V, X5R, ±10%, SMD 1206; Manufacturer: Taiyo Yuden; Manufacturer Part Number: EMK316BJ475KL-T
footprint CAP-1206 (1206 (3216M) Capacitor)
pins: 1, 2

## FM31N102J631EEG
designator C?  Capacitance: 1nF  (hidden comment: *)
Capacitor, Ceramic (MLCC), 1nF, ±5%, 630V, C0G, ±5%, SMD 1206; Manufacturer: PSA(Prosperity Dielectrics); Manufacturer Part Number: FM31N102J631EEG
footprint CAP-1206 (1206 (3216M) Capacitor)
pins: 1, 2

## FM31N103J101ECG
designator C?  Capacitance: 10nF  (hidden comment: *)
Capacitor, Ceramic (MLCC), 10nF, ±5%, 100V, NP0, ±5%, SMD 1206; Manufacturer: PSA(Prosperity Dielectrics); Manufacturer Part Number: FM31N103J101ECG
footprint CAP-1206 (1206 (3216M) Capacitor)
pins: 1, 2

## FM31N222J501EEG
designator C?  Capacitance: 2.2nF  (hidden comment: *)
Capacitor, Ceramic (MLCC), 2.2nF, ±5%, 500V, NP0, ±5%, SMD 1206; Manufacturer: PSA(Prosperity Dielectrics); Manufacturer Part Number: FM31N222J501EEG
footprint CAP-1206 (1206 (3216M) Capacitor)
pins: 1, 2

## FM31N222J631EEG
designator C?  Capacitance: 2.2nF  (hidden comment: *)
Capacitor, Ceramic (MLCC), 2.2nF, ±5%, 630V, NP0, ±5%, SMD 1206; Manufacturer: PSA(Prosperity Dielectrics); Manufacturer Part Number: FM31N222J631EEG
footprint CAP-1206 (1206 (3216M) Capacitor)
pins: 1, 2

## FM31N270J501PXG
designator C?  Capacitance: 27pF  (hidden comment: *)
Capacitor, Ceramic (MLCC), 27pF, ±5%, 500V, C0G, ±5%, SMD 1206; Manufacturer: PSA(Prosperity Dielectrics); Manufacturer Part Number: FM31N270J501PXG
footprint CAP-1206 (1206 (3216M) Capacitor)
pins: 1, 2

## FM31N471J501EMG
designator C?  Capacitance: 470pF  (hidden comment: *)
Capacitor, Ceramic (MLCC), 470pF, ±5%, 500V, C0G, ±5%, SMD 1206; Manufacturer: PSA(Prosperity Dielectrics); Manufacturer Part Number: FM31N471J501EMG
footprint CAP-1206 (1206 (3216M) Capacitor)
pins: 1, 2

## FM31N472J631EEG
designator C?  Capacitance: 4.7nF  (hidden comment: *)
Capacitor, Ceramic (MLCC), 4.7nF, ±5%, 630V, ±5%, SMD 1206; Manufacturer: PSA(Prosperity Dielectrics); Manufacturer Part Number: FM31N472J631EEG
footprint CAP-1206 (1206 (3216M) Capacitor)
pins: 1, 2

## FM31X102K201ECG
designator C?  Capacitance: 1nF  (hidden comment: *)
Capacitor, Ceramic (MLCC), 1nF, ±10%, 200V, X7R, ±10%, SMD 1206; Manufacturer: PSA(Prosperity Dielectrics); Manufacturer Part Number: FM31X102K201ECG
footprint CAP-1206 (1206 (3216M) Capacitor)
pins: 1, 2

## FM31X102K501ECG
designator C?  Capacitance: 1nF  (hidden comment: *)
Capacitor, Ceramic (MLCC), 1nF, ±10%, 500V, X7R, ±10%, SMD 1206; Manufacturer: PSA(Prosperity Dielectrics); Manufacturer Part Number: FM31X102K501ECG
footprint CAP-1206 (1206 (3216M) Capacitor)
pins: 1, 2

## FM31X103K251PXG
designator C?  Capacitance: 10nF  (hidden comment: *)
Capacitor, Ceramic (MLCC), 10nF, ±10%, 250V, X7R, ±10%, SMD 1206; Manufacturer: PSA(Prosperity Dielectrics); Manufacturer Part Number: FM31X103K251PXG
footprint CAP-1206 (1206 (3216M) Capacitor)
pins: 1, 2

## FM31X103K631ECG
designator C?  Capacitance: 10nF  (hidden comment: *)
Capacitor, Ceramic (MLCC), 10nF, ±10%, 630V, X7R, ±10%, SMD 1206; Manufacturer: PSA(Prosperity Dielectrics); Manufacturer Part Number: FM31X103K631ECG
footprint CAP-1206 (1206 (3216M) Capacitor)
pins: 1, 2

## FM31X104K101ECG
designator C?  Capacitance: 100nF  (hidden comment: *)
Capacitor, Ceramic (MLCC), 100nF, ±10%, 100V, X7R, ±10%, SMD 1206; Manufacturer: PSA(Prosperity Dielectrics); Manufacturer Part Number: FM31X104K101ECG
footprint CAP-1206 (1206 (3216M) Capacitor)
pins: 1, 2

## FM31X104K251EEG
designator C?  Capacitance: 100nF  (hidden comment: *)
Capacitor, Ceramic (MLCC), 100nF, ±10%, 250V, X7R, ±10%, SMD 1206; Manufacturer: PSA(Prosperity Dielectrics); Manufacturer Part Number: FM31X104K251EEG
footprint CAP-1206 (1206 (3216M) Capacitor)
pins: 1, 2

## FM31X104K451EEG
designator C?  Capacitance: 100nF  (hidden comment: *)
Capacitor, Ceramic (MLCC), 100nF, ±10%, 450V, X7R, ±10%, SMD 1206; Manufacturer: PSA(Prosperity Dielectrics); Manufacturer Part Number: FM31X104K451EEG
footprint CAP-1206 (1206 (3216M) Capacitor)
pins: 1, 2

## FM31X221K501ECG
designator C?  Capacitance: 220pF  (hidden comment: *)
Capacitor, Ceramic (MLCC), 220pF, ±10%, 500V, X7R, ±10%, SMD 1206; Manufacturer: PSA(Prosperity Dielectrics); Manufacturer Part Number: FM31X221K501ECG
footprint CAP-1206 (1206 (3216M) Capacitor)
pins: 1, 2

## FM31X223K201ECG
designator C?  Capacitance: 22nF  (hidden comment: *)
Capacitor, Ceramic (MLCC), 22nF, ±10%, 200V, X7R, ±10%, SMD 1206; Manufacturer: PSA(Prosperity Dielectrics); Manufacturer Part Number: FM31X223K201ECG
footprint CAP-1206 (1206 (3216M) Capacitor)
pins: 1, 2

## FM31X223K501EEG
designator C?  Capacitance: 22nF  (hidden comment: *)
Capacitor, Ceramic (MLCC), 22nF, ±10%, 500V, X7R, ±10%, SMD 1206; Manufacturer: PSA(Prosperity Dielectrics); Manufacturer Part Number: FM31X223K501EEG
footprint CAP-1206 (1206 (3216M) Capacitor)
pins: 1, 2

## FM31X223K631EEG
designator C?  Capacitance: 22nF  (hidden comment: *)
Capacitor, Ceramic (MLCC), 22nF, ±10%, 630V, X7R, ±10%, SMD 1206; Manufacturer: PSA(Prosperity Dielectrics); Manufacturer Part Number: FM31X223K631EEG
footprint CAP-1206 (1206 (3216M) Capacitor)
pins: 1, 2

## FM31X333K631EEG
designator C?  Capacitance: 33nF  (hidden comment: *)
Capacitor, Ceramic (MLCC), 33nF, ±10%, 630V, X7R, ±10%, SMD 1206; Manufacturer: PSA(Prosperity Dielectrics); Manufacturer Part Number: FM31X333K631EEG
footprint CAP-1206 (1206 (3216M) Capacitor)
pins: 1, 2

## FM31X473K251EEG
designator C?  Capacitance: 47nF  (hidden comment: *)
Capacitor, Ceramic (MLCC), 47nF, ±10%, 250V, X7R, ±10%, SMD 1206; Manufacturer: PSA(Prosperity Dielectrics); Manufacturer Part Number: FM31X473K251EEG
footprint CAP-1206 (1206 (3216M) Capacitor)
pins: 1, 2

## FM31X473K631EEG
designator C?  Capacitance: 47nF  (hidden comment: *)
Capacitor, Ceramic (MLCC), 47nF, ±10%, 630V, X7R, ±10%, SMD 1206; Manufacturer: PSA(Prosperity Dielectrics); Manufacturer Part Number: FM31X473K631EEG
footprint CAP-1206 (1206 (3216M) Capacitor)
pins: 1, 2

## FM31X683K201EEG
designator C?  Capacitance: 68nF  (hidden comment: *)
Capacitor, Ceramic (MLCC), 68nF, ±10%, 200V, X7R, ±10%, SMD 1206; Manufacturer: PSA(Prosperity Dielectrics); Manufacturer Part Number: FM31X683K201EEG
footprint CAP-1206 (1206 (3216M) Capacitor)
pins: 1, 2

## FM31X683K251EEG
designator C?  Capacitance: 68nF  (hidden comment: *)
Capacitor, Ceramic (MLCC), 68nF, ±10%, 250V, X7R, ±10%, SMD 1206; Manufacturer: PSA(Prosperity Dielectrics); Manufacturer Part Number: FM31X683K251EEG
footprint CAP-1206 (1206 (3216M) Capacitor)
pins: 1, 2

## FN31N222J500PXG
designator C?  Capacitance: 2.2nF  (hidden comment: *)
Capacitor, Ceramic (MLCC), 2.2nF, ±5%, 50V, NP0, ±5%, SMD 1206; Manufacturer: PSA(Prosperity Dielectrics); Manufacturer Part Number: FN31N222J500PXG
footprint CAP-1206 (1206 (3216M) Capacitor)
pins: 1, 2

## FN31N223J500EPG
designator C?  Capacitance: 22nF  (hidden comment: *)
Capacitor, Ceramic (MLCC), 22nF, ±5%, 50V, ±5%, SMD 1206; Manufacturer: PSA(Prosperity Dielectrics); Manufacturer Part Number: FN31N223J500EPG
footprint CAP-1206 (1206 (3216M) Capacitor)
pins: 1, 2

## FN31N823J500EPG
designator C?  Capacitance: 82nF  (hidden comment: *)
Capacitor, Ceramic (MLCC), 82nF, ±5%, 50V, C0G, ±5%, SMD 1206; Manufacturer: PSA(Prosperity Dielectrics); Manufacturer Part Number: FN31N823J500EPG
footprint CAP-1206 (1206 (3216M) Capacitor)
pins: 1, 2

## FN31X103K500PXG
designator C?  Capacitance: 10nF  (hidden comment: *)
Capacitor, Ceramic (MLCC), 10nF, ±10%, 50V, X7R, ±10%, SMD 1206; Manufacturer: PSA(Prosperity Dielectrics); Manufacturer Part Number: FN31X103K500PXG
footprint CAP-1206 (1206 (3216M) Capacitor)
pins: 1, 2

## FN31X104K500PXG
designator C?  Capacitance: 100nF  (hidden comment: *)
Capacitor, Ceramic (MLCC), 100nF, ±10%, 50V, X7R, ±10%, SMD 1206; Manufacturer: PSA(Prosperity Dielectrics); Manufacturer Part Number: FN31X104K500PXG
footprint CAP-1206 (1206 (3216M) Capacitor)
pins: 1, 2

## FN31X224K500EMG
designator C?  Capacitance: 220nF  (hidden comment: *)
Capacitor, Ceramic (MLCC), 220nF, ±10%, 50V, X7R, ±10%, SMD 1206; Manufacturer: PSA(Prosperity Dielectrics); Manufacturer Part Number: FN31X224K500EMG
footprint CAP-1206 (1206 (3216M) Capacitor)
pins: 1, 2

## FN31X474K500EPG
designator C?  Capacitance: 470nF  (hidden comment: *)
Capacitor, Ceramic (MLCC), 470nF, ±10%, 50V, X7R, ±10%, SMD 1206; Manufacturer: PSA(Prosperity Dielectrics); Manufacturer Part Number: FN31X474K500EPG
footprint CAP-1206 (1206 (3216M) Capacitor)
pins: 1, 2

## FP31N101J102PXG
designator C?  Capacitance: 100pF  (hidden comment: *)
Capacitor, Ceramic (MLCC), 100pF, ±5%, 1kV, NP0, ±5%, SMD 1206; Manufacturer: PSA(Prosperity Dielectrics); Manufacturer Part Number: FP31N101J102PXG
footprint CAP-1206 (1206 (3216M) Capacitor)
pins: 1, 2

## FS31B106K160EPG
designator C?  Capacitance: 10uF  (hidden comment: *)
Capacitor, Ceramic (MLCC), 10uF, ±10%, 16V, X5R, ±10%, SMD 1206; Manufacturer: PSA(Prosperity Dielectrics); Manufacturer Part Number: FS31B106K160EPG
footprint CAP-1206 (1206 (3216M) Capacitor)
pins: 1, 2

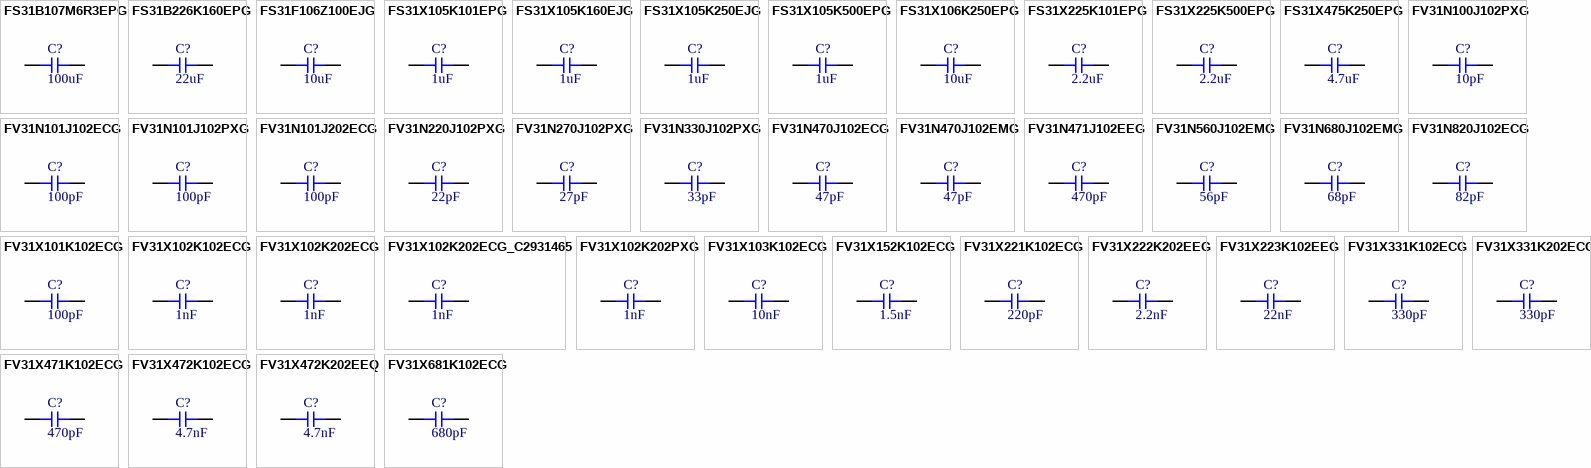
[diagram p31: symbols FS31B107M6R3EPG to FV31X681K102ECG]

## FS31B107M6R3EPG
designator C?  Capacitance: 100uF  (hidden comment: *)
Capacitor, Ceramic (MLCC), 100uF, ±20%, 6.3V, X5R, ±20%, SMD 1206; Manufacturer: PSA(Prosperity Dielectrics); Manufacturer Part Number: FS31B107M6R3EPG
footprint CAP-1206 (1206 (3216M) Capacitor)
pins: 1, 2

## FS31B226K160EPG
designator C?  Capacitance: 22uF  (hidden comment: *)
Capacitor, Ceramic (MLCC), 22uF, ±10%, 16V, X5R, ±10%, SMD 1206; Manufacturer: PSA(Prosperity Dielectrics); Manufacturer Part Number: FS31B226K160EPG
footprint CAP-1206 (1206 (3216M) Capacitor)
pins: 1, 2

## FS31F106Z100EJG
designator C?  Capacitance: 10uF  (hidden comment: *)
Capacitor, Ceramic (MLCC), 10uF, 10V, Y5V, SMD 1206; Manufacturer: PSA(Prosperity Dielectrics); Manufacturer Part Number: FS31F106Z100EJG; Temperature Rating: -20%~+80%
footprint CAP-1206 (1206 (3216M) Capacitor)
pins: 1, 2

## FS31X105K101EPG
designator C?  Capacitance: 1uF  (hidden comment: *)
Capacitor, Ceramic (MLCC), 1uF, ±10%, 100V, X7R, ±10%, SMD 1206; Manufacturer: PSA(Prosperity Dielectrics); Manufacturer Part Number: FS31X105K101EPG
footprint CAP-1206 (1206 (3216M) Capacitor)
pins: 1, 2

## FS31X105K160EJG
designator C?  Capacitance: 1uF  (hidden comment: *)
Capacitor, Ceramic (MLCC), 1uF, ±10%, 16V, X7R, ±10%, SMD 1206; Manufacturer: PSA(Prosperity Dielectrics); Manufacturer Part Number: FS31X105K160EJG
footprint CAP-1206 (1206 (3216M) Capacitor)
pins: 1, 2

## FS31X105K250EJG
designator C?  Capacitance: 1uF  (hidden comment: *)
Capacitor, Ceramic (MLCC), 1uF, ±10%, 25V, X7R, ±10%, SMD 1206; Manufacturer: PSA(Prosperity Dielectrics); Manufacturer Part Number: FS31X105K250EJG
footprint CAP-1206 (1206 (3216M) Capacitor)
pins: 1, 2

## FS31X105K500EPG
designator C?  Capacitance: 1uF  (hidden comment: *)
Capacitor, Ceramic (MLCC), 1uF, ±10%, 50V, X7R, ±10%, SMD 1206; Manufacturer: PSA(Prosperity Dielectrics); Manufacturer Part Number: FS31X105K500EPG
footprint CAP-1206 (1206 (3216M) Capacitor)
pins: 1, 2

## FS31X106K250EPG
designator C?  Capacitance: 10uF  (hidden comment: *)
Capacitor, Ceramic (MLCC), 10uF, ±10%, 25V, X7R, ±10%, SMD 1206; Manufacturer: PSA(Prosperity Dielectrics); Manufacturer Part Number: FS31X106K250EPG
footprint CAP-1206 (1206 (3216M) Capacitor)
pins: 1, 2

## FS31X225K101EPG
designator C?  Capacitance: 2.2uF  (hidden comment: *)
Capacitor, Ceramic (MLCC), 2.2uF, ±10%, 100V, ±10%, SMD 1206; Manufacturer: PSA(Prosperity Dielectrics); Manufacturer Part Number: FS31X225K101EPG
footprint CAP-1206 (1206 (3216M) Capacitor)
pins: 1, 2

## FS31X225K500EPG
designator C?  Capacitance: 2.2uF  (hidden comment: *)
Capacitor, Ceramic (MLCC), 2.2uF, ±10%, 50V, X7R, ±10%, SMD 1206; Manufacturer: PSA(Prosperity Dielectrics); Manufacturer Part Number: FS31X225K500EPG
footprint CAP-1206 (1206 (3216M) Capacitor)
pins: 1, 2

## FS31X475K250EPG
designator C?  Capacitance: 4.7uF  (hidden comment: *)
Capacitor, Ceramic (MLCC), 4.7uF, ±10%, 25V, X7R, ±10%, SMD 1206; Manufacturer: PSA(Prosperity Dielectrics); Manufacturer Part Number: FS31X475K250EPG
footprint CAP-1206 (1206 (3216M) Capacitor)
pins: 1, 2

## FV31N100J102PXG
designator C?  Capacitance: 10pF  (hidden comment: *)
Capacitor, Ceramic (MLCC), 10pF, ±5%, 1kV, C0G, ±5%, SMD 1206; Manufacturer: PSA(Prosperity Dielectrics); Manufacturer Part Number: FV31N100J102PXG
footprint CAP-1206 (1206 (3216M) Capacitor)
pins: 1, 2

## FV31N101J102ECG
designator C?  Capacitance: 100pF  (hidden comment: *)
Capacitor, Ceramic (MLCC), 100pF, ±5%, 1kV, C0G, ±5%, SMD 1206; Manufacturer: PSA(Prosperity Dielectrics); Manufacturer Part Number: FV31N101J102ECG
footprint CAP-1206 (1206 (3216M) Capacitor)
pins: 1, 2

## FV31N101J102PXG
designator C?  Capacitance: 100pF  (hidden comment: *)
Capacitor, Ceramic (MLCC), 100pF, ±5%, 1kV, C0G, ±5%, SMD 1206; Manufacturer: PSA(Prosperity Dielectrics); Manufacturer Part Number: FV31N101J102PXG
footprint CAP-1206 (1206 (3216M) Capacitor)
pins: 1, 2

## FV31N101J202ECG
designator C?  Capacitance: 100pF  (hidden comment: *)
Capacitor, Ceramic (MLCC), 100pF, ±5%, 2kV, C0G, ±5%, SMD 1206; Manufacturer: PSA(Prosperity Dielectrics); Manufacturer Part Number: FV31N101J202ECG
footprint CAP-1206 (1206 (3216M) Capacitor)
pins: 1, 2

## FV31N220J102PXG
designator C?  Capacitance: 22pF  (hidden comment: *)
Capacitor, Ceramic (MLCC), 22pF, ±5%, 1kV, C0G, ±5%, SMD 1206; Manufacturer: PSA(Prosperity Dielectrics); Manufacturer Part Number: FV31N220J102PXG
footprint CAP-1206 (1206 (3216M) Capacitor)
pins: 1, 2

## FV31N270J102PXG
designator C?  Capacitance: 27pF  (hidden comment: *)
Capacitor, Ceramic (MLCC), 27pF, ±5%, 1kV, C0G, ±5%, SMD 1206; Manufacturer: PSA(Prosperity Dielectrics); Manufacturer Part Number: FV31N270J102PXG
footprint CAP-1206 (1206 (3216M) Capacitor)
pins: 1, 2

## FV31N330J102PXG
designator C?  Capacitance: 33pF  (hidden comment: *)
Capacitor, Ceramic (MLCC), 33pF, ±5%, 1kV, C0G, ±5%, SMD 1206; Manufacturer: PSA(Prosperity Dielectrics); Manufacturer Part Number: FV31N330J102PXG
footprint CAP-1206 (1206 (3216M) Capacitor)
pins: 1, 2

## FV31N470J102ECG
designator C?  Capacitance: 47pF  (hidden comment: *)
Capacitor, Ceramic (MLCC), 47pF, ±5%, 1kV, C0G, ±5%, SMD 1206; Manufacturer: PSA(Prosperity Dielectrics); Manufacturer Part Number: FV31N470J102ECG
footprint CAP-1206 (1206 (3216M) Capacitor)
pins: 1, 2

## FV31N470J102EMG
designator C?  Capacitance: 47pF  (hidden comment: *)
Capacitor, Ceramic (MLCC), 47pF, ±5%, 1kV, C0G, ±5%, SMD 1206; Manufacturer: PSA(Prosperity Dielectrics); Manufacturer Part Number: FV31N470J102EMG
footprint CAP-1206 (1206 (3216M) Capacitor)
pins: 1, 2

## FV31N471J102EEG
designator C?  Capacitance: 470pF  (hidden comment: *)
Capacitor, Ceramic (MLCC), 470pF, ±5%, 1kV, C0G, ±5%, SMD 1206; Manufacturer: PSA(Prosperity Dielectrics); Manufacturer Part Number: FV31N471J102EEG
footprint CAP-1206 (1206 (3216M) Capacitor)
pins: 1, 2

## FV31N560J102EMG
designator C?  Capacitance: 56pF  (hidden comment: *)
Capacitor, Ceramic (MLCC), 56pF, ±5%, 1kV, C0G, ±5%, SMD 1206; Manufacturer: PSA(Prosperity Dielectrics); Manufacturer Part Number: FV31N560J102EMG
footprint CAP-1206 (1206 (3216M) Capacitor)
pins: 1, 2

## FV31N680J102EMG
designator C?  Capacitance: 68pF  (hidden comment: *)
Capacitor, Ceramic (MLCC), 68pF, ±5%, 1kV, C0G, ±5%, SMD 1206; Manufacturer: PSA(Prosperity Dielectrics); Manufacturer Part Number: FV31N680J102EMG
footprint CAP-1206 (1206 (3216M) Capacitor)
pins: 1, 2

## FV31N820J102ECG
designator C?  Capacitance: 82pF  (hidden comment: *)
Capacitor, Ceramic (MLCC), 82pF, ±5%, 1kV, NP0, ±5%, SMD 1206; Manufacturer: PSA(Prosperity Dielectrics); Manufacturer Part Number: FV31N820J102ECG
footprint CAP-1206 (1206 (3216M) Capacitor)
pins: 1, 2

## FV31X101K102ECG
designator C?  Capacitance: 100pF  (hidden comment: *)
Capacitor, Ceramic (MLCC), 100pF, ±10%, 1kV, X7R, ±10%, SMD 1206; Manufacturer: PSA(Prosperity Dielectrics); Manufacturer Part Number: FV31X101K102ECG
footprint CAP-1206 (1206 (3216M) Capacitor)
pins: 1, 2

## FV31X102K102ECG
designator C?  Capacitance: 1nF  (hidden comment: *)
Capacitor, Ceramic (MLCC), 1nF, ±10%, 1kV, X7R, ±10%, SMD 1206; Manufacturer: PSA(Prosperity Dielectrics); Manufacturer Part Number: FV31X102K102ECG
footprint CAP-1206 (1206 (3216M) Capacitor)
pins: 1, 2

## FV31X102K202ECG
designator C?  Capacitance: 1nF  (hidden comment: *)
Capacitor, Ceramic (MLCC), 1nF, ±10%, 2kV, X7R, ±10%, SMD 1206; Manufacturer: PSA(Prosperity Dielectrics); Manufacturer Part Number: FV31X102K202ECG
footprint CAP-1206 (1206 (3216M) Capacitor)
pins: 1, 2

## FV31X102K202ECG_C2931465
designator C?  Capacitance: 1nF  (hidden comment: *)
Capacitor, Ceramic (MLCC), 1nF, ±10%, 2kV, X7R, ±10%, SMD 1206; Manufacturer: Milliohm; Manufacturer Part Number: FV31X102K202ECG
footprint CAP-1206 (1206 (3216M) Capacitor)
pins: 1, 2

## FV31X102K202PXG
designator C?  Capacitance: 1nF  (hidden comment: *)
Capacitor, Ceramic (MLCC), 1nF, ±10%, 2kV, X7R, ±10%, SMD 1206; Manufacturer: PSA(Prosperity Dielectrics); Manufacturer Part Number: FV31X102K202PXG
footprint CAP-1206 (1206 (3216M) Capacitor)
pins: 1, 2

## FV31X103K102ECG
designator C?  Capacitance: 10nF  (hidden comment: *)
Capacitor, Ceramic (MLCC), 10nF, ±10%, 1kV, X7R, ±10%, SMD 1206; Manufacturer: PSA(Prosperity Dielectrics); Manufacturer Part Number: FV31X103K102ECG
footprint CAP-1206 (1206 (3216M) Capacitor)
pins: 1, 2

## FV31X152K102ECG
designator C?  Capacitance: 1.5nF  (hidden comment: *)
Capacitor, Ceramic (MLCC), 1.5nF, ±10%, 1kV, X7R, ±10%, SMD 1206; Manufacturer: PSA(Prosperity Dielectrics); Manufacturer Part Number: FV31X152K102ECG
footprint CAP-1206 (1206 (3216M) Capacitor)
pins: 1, 2

## FV31X221K102ECG
designator C?  Capacitance: 220pF  (hidden comment: *)
Capacitor, Ceramic (MLCC), 220pF, ±10%, 1kV, X7R, ±10%, SMD 1206; Manufacturer: PSA(Prosperity Dielectrics); Manufacturer Part Number: FV31X221K102ECG
footprint CAP-1206 (1206 (3216M) Capacitor)
pins: 1, 2

## FV31X222K202EEG
designator C?  Capacitance: 2.2nF  (hidden comment: *)
Capacitor, Ceramic (MLCC), 2.2nF, ±10%, 2kV, X7R, ±10%, SMD 1206; Manufacturer: PSA(Prosperity Dielectrics); Manufacturer Part Number: FV31X222K202EEG
footprint CAP-1206 (1206 (3216M) Capacitor)
pins: 1, 2

## FV31X223K102EEG
designator C?  Capacitance: 22nF  (hidden comment: *)
Capacitor, Ceramic (MLCC), 22nF, ±10%, 1kV, ±10%, SMD 1206; Manufacturer: PSA(Prosperity Dielectrics); Manufacturer Part Number: FV31X223K102EEG
footprint CAP-1206 (1206 (3216M) Capacitor)
pins: 1, 2

## FV31X331K102ECG
designator C?  Capacitance: 330pF  (hidden comment: *)
Capacitor, Ceramic (MLCC), 330pF, ±10%, 1kV, X7R, ±10%, SMD 1206; Manufacturer: PSA(Prosperity Dielectrics); Manufacturer Part Number: FV31X331K102ECG
footprint CAP-1206 (1206 (3216M) Capacitor)
pins: 1, 2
